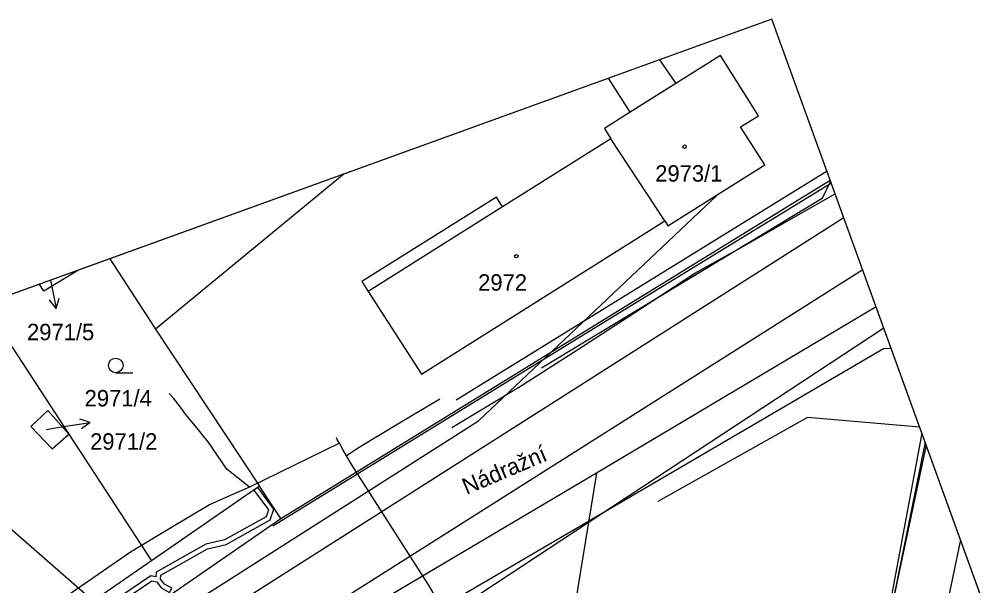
# Model space of a CAD drawing. Extents: x -620552 to -620056, y -1123312 to -1122890.
# Drawn here: x -620235.1 to -620136.2, y -1122948.3 to -1122889.6 of the extents above; entities that cross this region are included whole.
import ezdxf

# ---------------------------------------------------------------- set-up
doc = ezdxf.new("R2010")
doc.units = 0
for name, color, linetype in [('CD-T  SDK', 7, 'Continuous'), ('CETIN', 7, 'Continuous'), ('HranDP', 7, 'Continuous'), ('Hranice parcel', 7, 'Continuous'), ('Město Bystřice-osvětlení', 7, 'Continuous'), ('Parcelní čísla', 7, 'Continuous'), ('Pop  PČ popisy', 7, 'Continuous'), ('PS 06-14-01_trasa_sdělovací_nové', 7, 'Continuous'), ('Rámečky', 7, 'Continuous'), ('Rámečky-tisk', 7, 'Continuous'), ('SSZT-DK SDK', 7, 'Continuous'), ('SSZT-OSS', 7, 'Continuous'), ('VAS vodovod', 7, 'Continuous'), ('Vnitřní kresba', 7, 'Continuous'), ('Vrstva 1', 7, 'Continuous'), ('Věcná břemena k části', 7, 'Continuous'), ('Značky budov', 7, 'Continuous'), ('Značky kultur', 7, 'Continuous'), ('ČD-T OSS Ždár', 7, 'Continuous')]:
    doc.layers.add(name, color=color, linetype=linetype)

msp = doc.modelspace()

# ---------------------------------------------------------------- linework, layer by layer
at = {"layer": 'CD-T  SDK'}
msp.add_lwpolyline([(-620151.484, -1122905.358), (-620189.847, -1122929.066)], dxfattribs=at)
at = {"layer": 'CETIN'}
for points in [[(-620249.32, -1122970.47), (-620218.63, -1122950.99), (-620187.55, -1122931.18), (-620162.84, -1122907.83)], [(-620190.31, -1122931.88), (-620183.21, -1122927.61), (-620177.37, -1122923.89), (-620170.67, -1122919.52), (-620165.17, -1122915.89), (-620159.81, -1122912.93), (-620154.47, -1122909.86), (-620150.638, -1122907.695)], [(-620523.507, -1123111.553), (-620453.589, -1123102.463), (-620423.237, -1123094.915), (-620404.669, -1123086.509), (-620368.955, -1123067.056), (-620277.606, -1123008.491), (-620145.621, -1122921.549)]]:
    msp.add_lwpolyline(points, dxfattribs=at)
at = {"layer": 'HranDP'}
msp.add_lwpolyline([(-620141.663, -1122932.48), (-620145.74, -1122954.29), (-620154.8, -1122984.44), (-620166.17, -1123006.98), (-620184.51, -1123027.31)], dxfattribs=at)
at = {"layer": 'Hranice parcel'}
for p, q in [((-620208, -1122941.31), (-620151.155, -1122906.268)), ((-620225.706, -1122914.41), (-620220.99, -1122921.7)), ((-620146.402, -1122919.395), (-620175.35, -1122936.6)), ((-620220.99, -1122921.7), (-620210.21, -1122937.96)), ((-620210.21, -1122937.96), (-620221.39, -1122945.68)), ((-620208, -1122941.31), (-620210.21, -1122937.96)), ((-620251.74, -1122971.48), (-620208, -1122941.31)), ((-620221.39, -1122945.68), (-620235.69, -1122955.55))]:
    msp.add_line(p, q, dxfattribs=at)
for points in [[(-620168.81, -1122893.807), (-620167.12, -1122896.26), (-620171.85, -1122899.25), (-620174.084, -1122895.717)], [(-620198.98, -1122917.79), (-620193.45, -1122926.35), (-620168.27, -1122910.5), (-620173.85, -1122901.99), (-620185.06, -1122909.04), (-620185.7, -1122908.03), (-620199.62, -1122916.78), (-620198.98, -1122917.79)], [(-620201.435, -1122905.621), (-620220.99, -1122921.7)], [(-620228.954, -1122915.586), (-620232.52, -1122917.77), (-620232.965, -1122917.039)], [(-620238.742, -1122919.13), (-620229.95, -1122932.57), (-620221.39, -1122945.68)], [(-620229.95, -1122932.57), (-620232.13, -1122930.14), (-620233.86, -1122931.77)], [(-620233.86, -1122931.77), (-620231.67, -1122934.08), (-620229.95, -1122932.57)], [(-620141.663, -1122932.48), (-620145.74, -1122954.29), (-620154.8, -1122984.44), (-620166.17, -1123006.98), (-620184.51, -1123027.31)], [(-620175.35, -1122936.6), (-620194.44, -1122947.94), (-620201.16, -1122951.94)], [(-620175.35, -1122936.6), (-620186.12, -1123002.76), (-620194.62, -1123031.45)]]:
    msp.add_lwpolyline(points, dxfattribs=at)
at = {"layer": 'Město Bystřice-osvětlení'}
msp.add_lwpolyline([(-620151.04, -1122906.586), (-620174.136, -1122920.728), (-620208.83, -1122942.099)], dxfattribs=at)
at = {"layer": 'Pop  PČ popisy'}
for p, q in [((-620231.829, -1122916.627), (-620231.257, -1122919.566)), ((-620231.257, -1122919.566), (-620231.94, -1122918.678)), ((-620231.257, -1122919.566), (-620230.957, -1122918.487)), ((-620230.7, -1122931.83), (-620227.736, -1122931.361)), ((-620227.736, -1122931.361), (-620228.803, -1122931.023)), ((-620227.736, -1122931.361), (-620228.647, -1122932.012)), ((-620232.28, -1122932.09), (-620230.7, -1122931.83))]:
    msp.add_line(p, q, dxfattribs=at)
at = {"layer": 'PS 06-14-01_trasa_sdělovací_nové'}
msp.add_lwpolyline([(-620141.323, -1122933.42), (-620145.54, -1122954.13), (-620150.629, -1122971.371), (-620142.936, -1122974.459)], dxfattribs=at)
at = {"layer": 'Rámečky'}
for p, q in [((-620157.191, -1122889.6), (-620552.097, -1123032.599)), ((-620056.07, -1123168.855), (-620157.191, -1122889.6))]:
    msp.add_line(p, q, dxfattribs=at)
for points in [[(-620126.701, -1122973.8), (-620157.191, -1122889.6), (-620255.57, -1122925.224)], [(-620255.57, -1122925.224), (-620158.492, -1123010.143), (-620126.701, -1122973.8)]]:
    msp.add_lwpolyline(points, dxfattribs=at)
at = {"layer": 'Rámečky-tisk'}
for points in [[(-620450.976, -1123311.855), (-620056.07, -1123168.855), (-620157.191, -1122889.6), (-620552.097, -1123032.599)], [(-620126.701, -1122973.8), (-620157.191, -1122889.6), (-620255.57, -1122925.224)], [(-620255.57, -1122925.224), (-620158.492, -1123010.143), (-620126.701, -1122973.8)]]:
    msp.add_lwpolyline(points, dxfattribs=at)
at = {"layer": 'SSZT-DK SDK'}
msp.add_lwpolyline([(-620151.114, -1122906.382), (-620151.977, -1122908.188), (-620181.024, -1122925.755)], dxfattribs=at)
at = {"layer": 'SSZT-OSS'}
msp.add_lwpolyline([(-620141.891, -1122931.851), (-620153.493, -1122930.84), (-620168.985, -1122939.54)], dxfattribs=at)
at = {"layer": 'VAS vodovod'}
for points in [[(-620211.24, -1122938.06), (-620211.248, -1122938.049), (-620212.415, -1122937.13), (-620213.59, -1122936.2), (-620214.565, -1122934.785), (-620215.54, -1122933.37), (-620216.705, -1122931.93), (-620217.87, -1122930.49), (-620218.28, -1122929.92), (-620219.12, -1122928.86), (-620219.55, -1122928.37)], [(-620201.195, -1122934.804), (-620201.05, -1122934.69), (-620200.475, -1122934.305), (-620199.9, -1122933.92), (-620195.711, -1122931.413), (-620191.56, -1122928.93)], [(-620186.395, -1122959.115), (-620192.67, -1122948.28), (-620196.69, -1122941.97), (-620200.71, -1122935.66), (-620201.195, -1122934.804), (-620201.573, -1122934.147), (-620201.95, -1122933.49), (-620206.595, -1122935.775), (-620211.24, -1122938.06), (-620213.315, -1122938.975), (-620215.39, -1122939.89), (-620219.475, -1122942.335), (-620223.56, -1122944.78), (-620227.81, -1122947.715), (-620232.06, -1122950.65)], [(-620201.95, -1122933.49), (-620202.055, -1122933.31), (-620202.16, -1122933.13), (-620202.26, -1122932.96)]]:
    msp.add_lwpolyline(points, dxfattribs=at)
at = {"layer": 'Vnitřní kresba'}
for p, q in [((-620162.51, -1122893.37), (-620167.12, -1122896.26)), ((-620158.59, -1122899.61), (-620162.51, -1122893.37)), ((-620171.85, -1122899.25), (-620174.52, -1122900.92)), ((-620160.44, -1122900.76), (-620158.59, -1122899.61)), ((-620174.52, -1122900.92), (-620173.85, -1122901.99)), ((-620157.94, -1122904.69), (-620160.44, -1122900.76)), ((-620167.95, -1122911), (-620157.94, -1122904.69)), ((-620185.06, -1122909.04), (-620198.98, -1122917.79)), ((-620149.743, -1122910.169), (-620224.19, -1122957.54)), ((-620168.27, -1122910.5), (-620167.95, -1122911)), ((-620147.785, -1122915.574), (-620220.18, -1122961.38))]:
    msp.add_line(p, q, dxfattribs=at)
at = {"layer": 'Vrstva 1'}
for points in [[(-620150.629, -1122971.371), (-620145.98, -1122955.43), (-620145.54, -1122954.13), (-620141.24, -1122933.85), (-620141.215, -1122933.718)], [(-620137.668, -1122943.514), (-620139.253, -1122951.105), (-620141.182, -1122958.739), (-620143.492, -1122966.59), (-620145.521, -1122972.655), (-620147.957, -1122979.169), (-620151.126, -1122986.803), (-620154.498, -1122994.077), (-620158.348, -1123001.534), (-620162.369, -1123008.603), (-620164.312, -1123011.799), (-620168.876, -1123018.81), (-620173.503, -1123025.274), (-620178.73, -1123032.025), (-620183.711, -1123037.931), (-620189.421, -1123044.163), (-620195.408, -1123050.18)]]:
    msp.add_lwpolyline(points, dxfattribs=at)
at = {"layer": 'Věcná břemena k části'}
msp.add_lwpolyline([(-620238.02, -1122959.05), (-620221.34, -1122947.77), (-620220.85, -1122947.88), (-620220.38, -1122948.48), (-620219.54, -1122948.96), (-620219.3, -1122948.52), (-620220.04, -1122948.1), (-620220.45, -1122947.58), (-620220.43, -1122947.18), (-620215.58, -1122944.45), (-620213.67, -1122944.01), (-620209.12, -1122941.46), (-620208.72, -1122940.34), (-620210.39, -1122938.08), (-620210.8, -1122938.37), (-620209.28, -1122940.42), (-620209.52, -1122941.12), (-620213.85, -1122943.53), (-620215.76, -1122943.97), (-620220.91, -1122946.88), (-620220.94, -1122947.35), (-620221.44, -1122947.23), (-620238.3, -1122958.63)], dxfattribs=at)
at = {"layer": 'Značky budov'}
for centre in [(-620166.227, -1122902.809), (-620183.637, -1122914.159)]:
    msp.add_circle(centre, 0.175, dxfattribs=at)
at = {"layer": 'Značky kultur'}
msp.add_line((-620225.083, -1122926.21), (-620223.333, -1122926.21), dxfattribs=at)
msp.add_circle((-620225.083, -1122925.46), 0.75, dxfattribs=at)
at = {"layer": 'ČD-T OSS Ždár'}
msp.add_lwpolyline([(-620144.839, -1122923.711), (-620145.628, -1122923.723), (-620198.095, -1122954.464)], dxfattribs=at)

# ---------------------------------------------------------------- texts
at = {"layer": 'Parcelní čísla'}
for s, p in [('2973/1', (-620169.265, -1122906.426)), ('2972', (-620187.587, -1122917.716)), ('2971/5', (-620234.265, -1122922.85)), ('2971/4', (-620228.305, -1122929.7)), ('2971/2', (-620227.74, -1122934.183))]:
    msp.add_text(s, height=1.7, dxfattribs=at).set_placement(p)
at = {"layer": 'Pop  PČ popisy'}
msp.add_text('Nádražní', height=1.7, rotation=23, dxfattribs=at).set_placement((-620188.79, -1122938.867))

doc.saveas('drawing.dxf')
